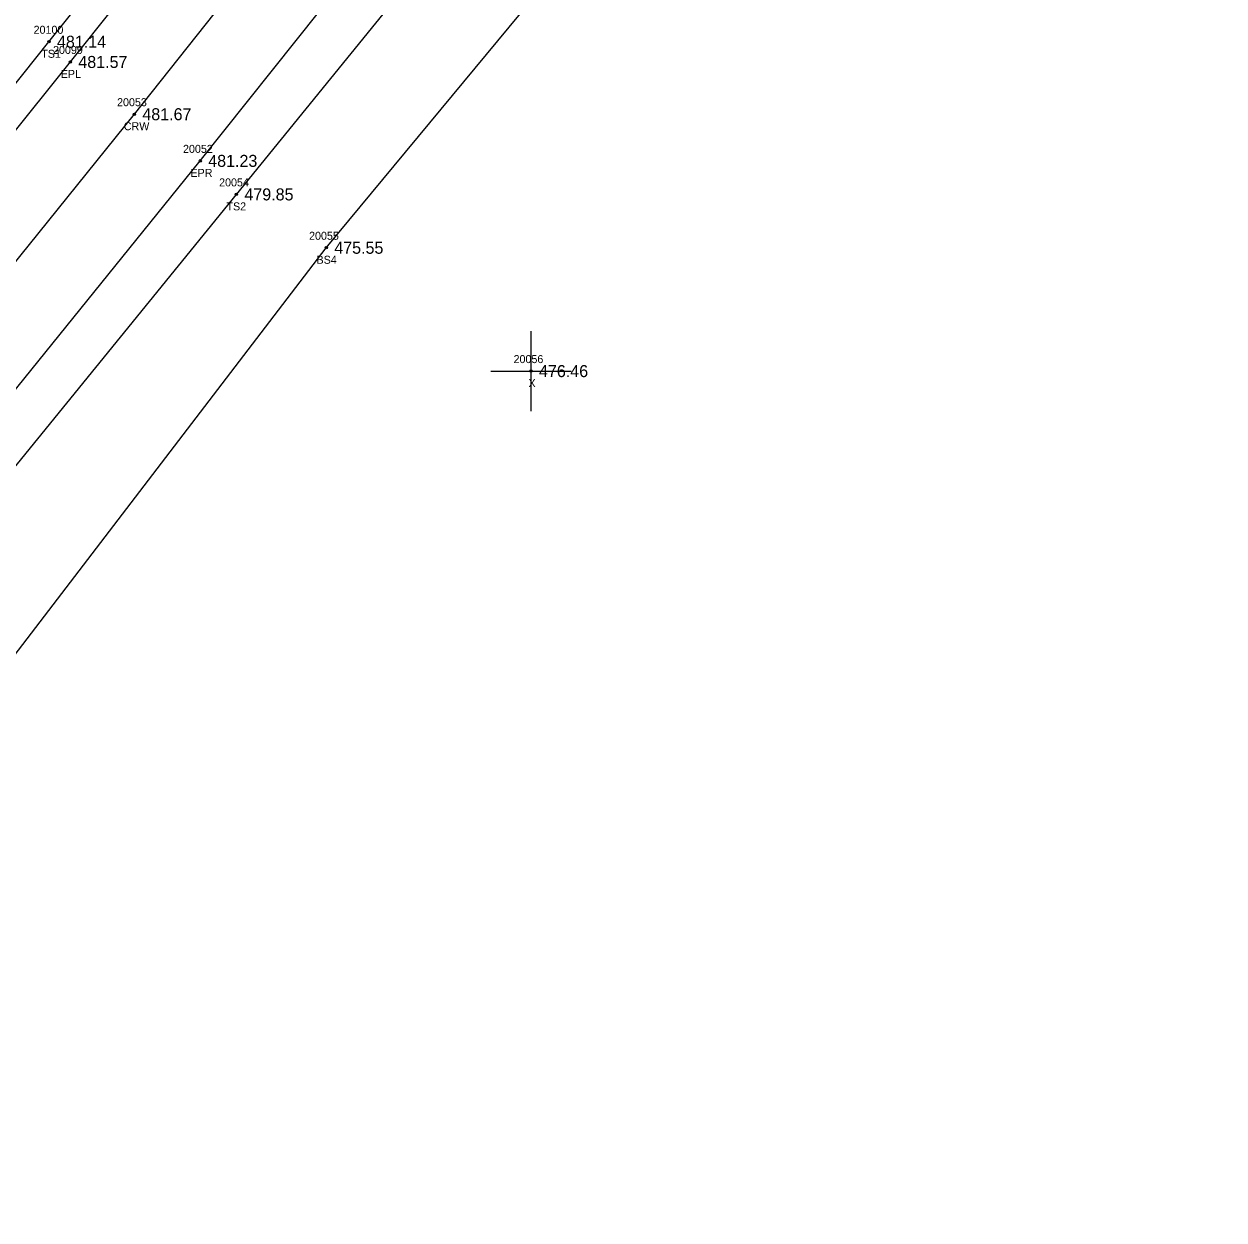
# Model space of a CAD drawing. Extents: x 1789565 to 1790548, y 909019 to 910194.
# Drawn here: x 1789914 to 1790064, y 909307.2 to 909456.7 of the extents above; entities that cross this region are included whole.
import ezdxf

# ---------------------------------------------------------------- set-up
doc = ezdxf.new("R2010")
doc.units = 0
for name, color, linetype in [('RD_DTM_BkLn1', 7, 'Continuous'), ('RD_DTM_BkLn2', 7, 'Continuous'), ('RD_DTM_BkLn_txCode', 7, 'Continuous'), ('RD_EX_Misc', 7, 'Continuous'), ('RD_EX_Misc_txCode', 7, 'Continuous'), ('RD_EX_Road', 7, 'Continuous'), ('RD_EX_Road_txCode', 7, 'Continuous'), ('RD_EX_TX_Misc_ELEV', 7, 'Continuous'), ('RD_EX_TX_Road_ELEV', 7, 'Continuous'), ('RD_HC_Survey_ELEV', 7, 'Continuous'), ('RD_HC_Survey_txCode', 7, 'Continuous'), ('RD_SMD_Locator', 7, 'Continuous')]:
    doc.layers.add(name, color=color, linetype=linetype)

msp = doc.modelspace()

# ---------------------------------------------------------------- linework, layer by layer
at = {"layer": 'RD_DTM_BkLn1'}
msp.add_lwpolyline([(1789624.5, 909066.24), (1789686.15, 909143.09), (1789745.11, 909217.37), (1789803.6, 909290.4), (1789864.63, 909366.97), (1789927.82, 909445.41), (1789987.57, 909520.69), (1790044.94, 909592.68)], dxfattribs=at)
at = {"layer": 'RD_DTM_BkLn2'}
for points in [[(1789902.5, 909352.17), (1789901.93, 909363.56), (1789951.8, 909428.72), (1790013.3, 909502.93), (1790049.48, 909550.91), (1790055.89, 909557.37), (1790063.97, 909580.51), (1790058.82, 909587.37), (1790034.63, 909603.55)], [(1789614.08, 909073.14), (1789676.68, 909150.35), (1789735.2, 909226.02), (1789793.81, 909297.32), (1789853.39, 909374.42), (1789917.15, 909454.46), (1789977.25, 909529.33), (1790025.37, 909589.9), (1790030.46, 909600.52), (1790034.43, 909600.71)], [(1789900.24, 909342.75), (1789881.76, 909350.91), (1789880.04, 909360.95), (1789940.57, 909435.39), (1790001.5, 909510.33), (1790055.89, 909575.68), (1790057.84, 909580.4), (1790055.44, 909584.35)]]:
    msp.add_lwpolyline(points, dxfattribs=at)
at = {"layer": 'RD_EX_Misc'}
for p, q in [((1789977.38, 909408.31), (1789977.38, 909418.31)), ((1789972.38, 909413.31), (1789982.38, 909413.31))]:
    msp.add_line(p, q, dxfattribs=at)
at = {"layer": 'RD_EX_Road'}
for points in [[(1789616.04, 909073.03), (1789678, 909149.36), (1789737.65, 909223.89), (1789795.32, 909296.33), (1789856.01, 909372.29), (1789919.82, 909451.94), (1789979.86, 909527.13), (1790037.32, 909598.58), (1790044.94, 909592.68)], [(1789632.25, 909060.17), (1789693.63, 909136.51), (1789752.94, 909210.84), (1789811.79, 909284.47), (1789846.6, 909328.43), (1789872.88, 909361.39), (1789936.05, 909439.58), (1789995.85, 909514.58), (1790052.72, 909586.51), (1790044.94, 909592.68)]]:
    msp.add_lwpolyline(points, dxfattribs=at)
at = {"layer": 'RD_SMD_Locator'}
for centre in [(1789917.15, 909454.46), (1789919.82, 909451.94), (1789927.82, 909445.41), (1789936.05, 909439.58), (1789940.57, 909435.39), (1789951.8, 909428.72), (1789977.38, 909413.31)]:
    msp.add_circle(centre, 0.15, dxfattribs=at)

# ---------------------------------------------------------------- texts
at = {"layer": 'RD_DTM_BkLn_txCode'}
for s, p in [('20100', (1789915.23, 909455.46)), ('TS1', (1789916.19, 909452.46)), ('20054', (1789938.41, 909436.39)), ('TS2', (1789939.33, 909433.39)), ('20055', (1789949.65, 909429.72)), ('BS4', (1789950.58, 909426.72))]:
    msp.add_text(s, height=1, dxfattribs=at).set_placement(p)
at = {"layer": 'RD_EX_Misc_txCode'}
for s, p in [('20056', (1789975.2, 909414.31)), ('X', (1789977.06, 909411.31))]:
    msp.add_text(s, height=1, dxfattribs=at).set_placement(p)
at = {"layer": 'RD_EX_Road_txCode'}
for s, p in [('20099', (1789917.66, 909452.94)), ('EPL', (1789918.62, 909449.94)), ('20052', (1789933.9, 909440.58)), ('EPR', (1789934.83, 909437.58))]:
    msp.add_text(s, height=1, dxfattribs=at).set_placement(p)
at = {"layer": 'RD_EX_TX_Misc_ELEV'}
for s, p in [('481.14', (1789918.15, 909453.71)), ('479.85', (1789941.57, 909434.64)), ('475.55', (1789952.8, 909427.97)), ('476.46', (1789978.38, 909412.56))]:
    msp.add_text(s, height=1.5, dxfattribs=at).set_placement(p)
at = {"layer": 'RD_EX_TX_Road_ELEV'}
for s, p in [('481.57', (1789920.82, 909451.19)), ('481.23', (1789937.05, 909438.83))]:
    msp.add_text(s, height=1.5, dxfattribs=at).set_placement(p)
at = {"layer": 'RD_HC_Survey_ELEV'}
msp.add_text('481.67', height=1.5, dxfattribs=at).set_placement((1789928.82, 909444.66))
at = {"layer": 'RD_HC_Survey_txCode'}
for s, p in [('20053', (1789925.66, 909446.41)), ('CRW', (1789926.5, 909443.41))]:
    msp.add_text(s, height=1, dxfattribs=at).set_placement(p)

doc.saveas('drawing.dxf')
